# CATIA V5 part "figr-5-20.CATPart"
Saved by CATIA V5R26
Part number: Part1
Bounding box of the stored display mesh (mm): x -89.73 to 98.105, y -54.237 to 64.207, z 0 to 103
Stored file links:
  D:\_Deepak\CATIA\CATIA V5-6R2016_Deepak\Resources\Part files\Partfiles\c05_catia_v5_6r2016_prt\figr-5-20.CATPart
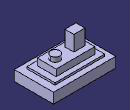
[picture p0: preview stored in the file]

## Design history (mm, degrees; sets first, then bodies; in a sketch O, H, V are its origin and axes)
Body1 (main body)
  Sketch1 on xy-plane, origin (0, 0, 0), H (1, 0, 0), V (0, 1, 0)
    line L1 (-89.7304, 64.2071) -> (98.1053, 64.2071)
    line L2 (98.1053, 64.2071) -> (98.1053, -54.2371)
    line L3 (98.1053, -54.2371) -> (-89.7304, -54.2371)
    line L4 (-89.7304, -54.2371) -> (-89.7304, 64.2071)
    line L5 (-72.4817, 47.8756) -> (77.1251, 47.8756)
    line L6 (77.1251, 47.8756) -> (77.1251, -36.7263)
    line L7 (77.1251, -36.7263) -> (-72.4817, -36.7263)
    line L8 (-72.4817, -36.7263) -> (-72.4817, 47.8756)
    line L9 (-57.1864, 33.5363) -> (59.44, 33.5363)
    line L10 (59.44, 33.5363) -> (59.44, -23.821)
    line L11 (59.44, -23.821) -> (-57.1864, -23.821)
    line L12 (-57.1864, -23.821) -> (-57.1864, 33.5363)
    circle A1 centre (34.1072, 5.3356) radius 13.9353
    line L13 (-44.759, 16.3291) -> (-11.3006, 16.3291)
    line L14 (-11.3006, 16.3291) -> (-11.3006, -10.9156)
    line L15 (-11.3006, -10.9156) -> (-44.759, -10.9156)
    line L16 (-44.759, -10.9156) -> (-44.759, 16.3291)
    horizontal: L1 H, L3 H, L5 H, L7 H, L9 H, L11 H, L13 H, L15 H
    vertical: L4 V, L6 V, L8 V, L10 V, L12 V, L14 V, L16 V
  MultiPad1: profile Sketch1, domains (length 103; length 57; length 0 / length -37; length 31; length 71)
